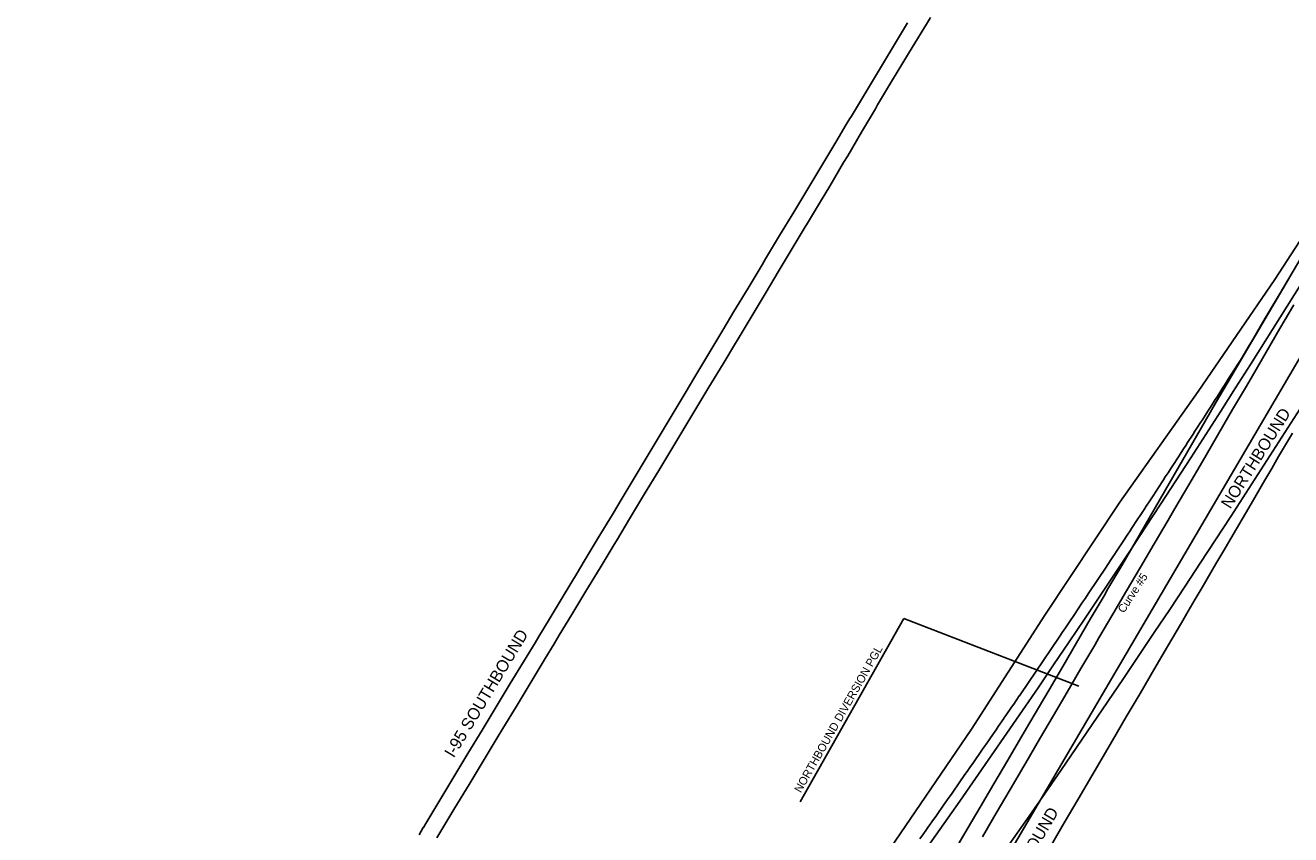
# Model space of a CAD drawing. Extents: x 1160458 to 1162290, y 615427 to 618737.
# Drawn here: x 1161573.3 to 1162037.4, y 618140.3 to 618437 of the extents above; entities that cross this region are included whole.
import ezdxf

# ---------------------------------------------------------------- set-up
doc = ezdxf.new("R2010")
doc.units = 0
for name, color, linetype in [('1', 7, 'Continuous'), ('ANNOTATION', 7, 'Continuous'), ('D_Roadway_Edge_Shoulder', 7, 'Continuous'), ('D_Roadway_Edge_TW', 7, 'Continuous'), ('D_Slope_Fill', 7, 'Continuous'), ('D_Text_Standard', 7, 'Continuous'), ('Old pavement area_not used', 7, 'Continuous'), ('Shoulder work for div plan (NB)', 7, 'Continuous'), ('Shoulder work for div plans (SB)', 7, 'Continuous')]:
    doc.layers.add(name, color=color, linetype=linetype)

msp = doc.modelspace()

# ---------------------------------------------------------------- linework, layer by layer
at = {"layer": '1'}
msp.add_line((1161209.81, 616899.51), (1162286.6, 618733.81), dxfattribs=at)
at = {"layer": 'D_Roadway_Edge_Shoulder'}
msp.add_lwpolyline([(1161901.43, 618138.75), (1161902.72, 618140.58), (1161903.54, 618141.74), (1161904.32, 618142.85), (1161906.43, 618145.84), (1161907.21, 618146.95), (1161908.5, 618148.79), (1161909.31, 618149.95), (1161910.09, 618151.05), (1161912.19, 618154.06), (1161912.97, 618155.16), (1161914.25, 618157), (1161915.07, 618158.17), (1161915.84, 618159.27), (1161917.94, 618162.28), (1161918.71, 618163.38), (1161919.99, 618165.23), (1161920.8, 618166.4), (1161921.57, 618167.5), (1161923.66, 618170.52), (1161924.42, 618171.62), (1161925.36, 618172.97), (1161925.7, 618173.47), (1161926.51, 618174.64), (1161926.54, 618174.67), (1161927.28, 618175.74), (1161929.36, 618178.76), (1161930.12, 618179.87), (1161932.2, 618182.89), (1161932.23, 618182.93), (1161932.96, 618184), (1161935.04, 618187.02), (1161935.8, 618188.13), (1161937.87, 618191.16), (1161937.9, 618191.2), (1161938.63, 618192.27), (1161940.7, 618195.3), (1161941.46, 618196.41), (1161943.53, 618199.44), (1161943.55, 618199.48), (1161944.28, 618200.55), (1161946.35, 618203.59), (1161947.1, 618204.7), (1161949.16, 618207.74), (1161949.18, 618207.77), (1161949.91, 618208.85), (1161951.97, 618211.9), (1161952.72, 618213), (1161953.64, 618214.36), (1161954.77, 618216.05), (1161954.79, 618216.08), (1161955.52, 618217.15), (1161956.51, 618218.64), (1161957.58, 618220.22), (1161958.31, 618221.31), (1161960.37, 618224.38), (1161961.1, 618225.47), (1161962.1, 618226.96), (1161963.16, 618228.55), (1161963.89, 618229.63), (1161965.95, 618232.72), (1161966.67, 618233.8), (1161967.66, 618235.29), (1161968.73, 618236.9), (1161969.44, 618237.97), (1161971.5, 618241.07), (1161972.21, 618242.14), (1161973.04, 618243.39), (1161973.2, 618243.63), (1161976.05, 618247.95), (1161977.44, 618250.04), (1161978.72, 618251.99), (1161978.82, 618252.14), (1161981.39, 618256.05), (1161982.22, 618257.32), (1161983.13, 618258.7), (1161983.91, 618259.89), (1161984.21, 618260.35), (1161985.97, 618263.03), (1161986.95, 618264.54), (1161988.02, 618266.17), (1161988.7, 618267.21), (1161990.75, 618270.36), (1161991.43, 618271.41), (1161992.42, 618272.92), (1161993.48, 618274.55), (1161994.16, 618275.6), (1161996.2, 618278.75), (1161996.88, 618279.8), (1161997.86, 618281.31), (1161998.92, 618282.94), (1161999.6, 618284), (1162001.63, 618287.14), (1162002.31, 618288.2), (1162003.29, 618289.72), (1162004.33, 618291.35), (1162004.35, 618291.37), (1162005.02, 618292.42), (1162007.04, 618295.56), (1162007.72, 618296.63), (1162008.62, 618298.03), (1162009.73, 618299.77), (1162009.75, 618299.8), (1162010.42, 618300.84), (1162012.43, 618303.99), (1162013.11, 618305.06), (1162015.11, 618308.21), (1162015.13, 618308.24), (1162019.8, 618315.58)], dxfattribs=at)
at = {"layer": 'D_Roadway_Edge_TW'}
for radius in [4188, 4212]:
    msp.add_arc((1158484.81, 620553.82), radius, 320.71863, 329.58575, dxfattribs=at)
at = {"layer": 'D_Slope_Fill'}
msp.add_lwpolyline([(1161864.33, 618096.78), (1161892.38, 618137.82), (1161920.38, 618178.92), (1161947.2, 618220.79), (1161974.76, 618262.22), (1162003.5, 618302.78), (1162031.65, 618343.82), (1162058.74, 618385.58), (1162080.66, 618419.35), (1162091.79, 618436.2), (1162091.79, 618436.2)], dxfattribs=at)
at = {"layer": 'D_Text_Standard'}
for p, q in [((1161857.43, 618152.36), (1161895.51, 618219.49)), ((1161895.51, 618219.49), (1161959.65, 618194.7))]:
    msp.add_line(p, q, dxfattribs=at)
at = {"layer": 'Old pavement area_not used'}
for points in [[(1162038.3, 618346.83), (1162033.2, 618338.23), (1162028.1, 618329.63), (1162023.01, 618321.02), (1162022.22, 618319.67), (1162017.16, 618311.05), (1162015.15, 618307.6), (1162010.12, 618298.96), (1162007.84, 618295), (1162002.84, 618286.34), (1161997.84, 618277.68), (1161992.87, 618269.04), (1161987.86, 618260.38), (1161985.49, 618256.3), (1161980.47, 618247.65), (1161975.44, 618239.01), (1161970.4, 618230.37), (1161968.95, 618227.89), (1161963.91, 618219.25), (1161958.86, 618210.62), (1161953.81, 618201.98), (1161948.76, 618193.35), (1161946.83, 618190.06), (1161941.78, 618181.44), (1161936.72, 618172.81), (1161933.64, 618167.57), (1161928.57, 618158.95), (1161923.5, 618150.33), (1161919.14, 618142.92), (1161914.07, 618134.3)], [(1161949.3, 618135.97), (1161954.35, 618144.59), (1161959.41, 618153.22), (1161964.46, 618161.85), (1161972.04, 618174.79), (1161977.1, 618183.42), (1161982.15, 618192.05), (1161987.21, 618200.68), (1161992.26, 618209.31), (1161997.32, 618217.94), (1161999.84, 618222.25), (1162002.37, 618226.57), (1162004.9, 618230.88), (1162009.95, 618239.51), (1162012.48, 618243.82), (1162017.53, 618252.45), (1162022.89, 618261.61), (1162027.94, 618270.24), (1162030.47, 618274.55), (1162033, 618278.87), (1162038.05, 618287.5)]]:
    msp.add_lwpolyline(points, dxfattribs=at)
at = {"layer": 'Shoulder work for div plan (NB)'}
msp.add_line((1162035.75, 618342.53), (1162008.98, 618296.98), dxfattribs=at)
for points in [[(1162073.95, 618408), (1162071.68, 618404.02), (1162069.4, 618400.04), (1162066.43, 618394.87), (1162061.43, 618386.21), (1162060.67, 618384.91), (1162058.15, 618380.58), (1162055.63, 618376.26), (1162052.51, 618370.92), (1162047.43, 618362.29), (1162042.35, 618353.68), (1162038.3, 618346.83), (1162035.75, 618342.53)], [(1161924.35, 618139.51), (1161929.4, 618148.14), (1161934.46, 618156.77), (1161939.51, 618165.4), (1161940.25, 618166.66), (1161945.31, 618175.29), (1161950.36, 618183.92), (1161955.42, 618192.54), (1161960.47, 618201.17), (1161965.54, 618209.8), (1161967.09, 618212.44), (1161972.16, 618221.07), (1161977.22, 618229.69), (1161982.29, 618238.31), (1161987.36, 618246.93), (1161992.42, 618255.55), (1161994.95, 618259.87), (1162000, 618268.5), (1162005.04, 618277.14), (1162010.08, 618285.77), (1162011.07, 618287.46), (1162016.12, 618296.1), (1162021.17, 618304.73), (1162023.41, 618308.55), (1162028.45, 618317.19), (1162033.49, 618325.83), (1162038.52, 618334.47)], [(1162008.98, 618296.98), (1162007.84, 618295), (1162002.84, 618286.34), (1161997.84, 618277.68), (1161992.87, 618269.04), (1161987.86, 618260.38), (1161985.49, 618256.3), (1161980.47, 618247.65), (1161975.44, 618239.01), (1161970.4, 618230.37), (1161968.95, 618227.89), (1161963.91, 618219.25), (1161958.86, 618210.62), (1161953.81, 618201.98), (1161948.76, 618193.35), (1161946.83, 618190.06), (1161941.78, 618181.44), (1161936.72, 618172.81), (1161933.64, 618167.57), (1161928.57, 618158.95), (1161923.5, 618150.33), (1161919.14, 618142.92), (1161915.96, 618137.52)]]:
    msp.add_lwpolyline(points, dxfattribs=at)
at = {"layer": 'Shoulder work for div plans (SB)'}
for p, q in [((1161895.18, 618423.29), (1161898.6, 618428.91)), ((1161891.03, 618416.44), (1161895.18, 618423.29)), ((1161885.91, 618407.85), (1161891.03, 618416.44)), ((1161885.07, 618406.43), (1161885.91, 618407.85)), ((1161875.74, 618402.79), (1161874.41, 618400.59)), ((1161876.26, 618403.65), (1161875.74, 618402.79)), ((1161865.43, 618385.66), (1161860.27, 618377.09)), ((1161868.33, 618378.08), (1161873.42, 618386.69)), ((1161864.94, 618372.4), (1161868.33, 618378.08)), ((1161860.27, 618377.09), (1161855.12, 618368.52)), ((1161855.12, 618368.52), (1161849.96, 618359.95)), ((1161849.96, 618359.95), (1161844.81, 618351.38)), ((1161844.67, 618338.62), (1161849.82, 618347.19)), ((1161838.35, 618340.64), (1161833.2, 618332.07)), ((1161839.51, 618330.05), (1161844.67, 618338.62)), ((1161834.35, 618321.49), (1161839.51, 618330.05)), ((1161829.18, 618312.92), (1161833.74, 618320.48)), ((1161833.74, 618320.48), (1161834.35, 618321.49)), ((1161824.02, 618304.36), (1161829.18, 618312.92)), ((1161818.86, 618308.14), (1161815.27, 618302.15)), ((1161804.99, 618284.99), (1161799.85, 618276.42)), ((1161799.85, 618276.42), (1161797.34, 618272.24)), ((1161797.34, 618272.24), (1161792.2, 618263.66)), ((1161792.2, 618263.66), (1161788.6, 618257.68)), ((1161784.1, 618238.1), (1161789.28, 618246.66)), ((1161778.29, 618240.54), (1161775.75, 618236.33)), ((1161775.75, 618236.33), (1161770.58, 618227.77)), ((1161778.92, 618229.55), (1161784.1, 618238.1)), ((1161773.74, 618221), (1161778.92, 618229.55)), ((1161770.58, 618227.77), (1161765.41, 618219.21)), ((1161765.41, 618219.21), (1161761.63, 618212.96)), ((1161760.24, 618210.65), (1161755.06, 618202.1)), ((1161761.63, 618212.96), (1161760.24, 618210.65)), ((1161755.06, 618202.1), (1161751.17, 618195.65)), ((1161751.17, 618195.65), (1161745.99, 618187.1)), ((1161753.62, 618187.72), (1161758.78, 618196.28)), ((1161748.45, 618179.16), (1161753.62, 618187.72)), ((1161745.99, 618187.1), (1161740.82, 618178.54)), ((1161740.82, 618178.54), (1161735.64, 618169.98)), ((1161746.39, 618175.75), (1161748.45, 618179.16)), ((1161735.64, 618169.98), (1161730.47, 618161.42)), ((1161730.47, 618161.42), (1161725.3, 618152.87)), ((1161725.3, 618152.87), (1161720.12, 618144.31)), ((1161719.24, 618142.84), (1161717.68, 618140.26)), ((1161719.3, 618142.94), (1161719.24, 618142.84)), ((1161720.12, 618144.31), (1161719.3, 618142.94)), ((1161724.24, 618139.12), (1161725.69, 618141.52))]:
    msp.add_line(p, q, dxfattribs=at)
for points in [[(1161898.6, 618428.91), (1161903.8, 618437.46), (1161905.29, 618439.91)], [(1161896.89, 618437.92), (1161891.73, 618429.35), (1161886.57, 618420.78)], [(1161886.57, 618420.78), (1161881.41, 618412.22), (1161876.26, 618403.65)], [(1161879.97, 618397.81), (1161879.98, 618397.82), (1161885.07, 618406.43)], [(1161874.41, 618400.59), (1161870.58, 618394.23), (1161865.43, 618385.66)], [(1161873.42, 618386.69), (1161874.91, 618389.2), (1161879.97, 618397.81)], [(1161849.82, 618347.19), (1161854.6, 618355.13), (1161859.74, 618363.7), (1161859.81, 618363.81), (1161864.94, 618372.4)], [(1161844.81, 618351.38), (1161843.5, 618349.21), (1161838.35, 618340.64)], [(1161833.2, 618332.07), (1161829.14, 618325.29), (1161824, 618316.71), (1161818.86, 618308.14)], [(1161810.74, 618282.33), (1161813.69, 618287.23), (1161818.86, 618295.79), (1161824.02, 618304.36)], [(1161815.27, 618302.15), (1161810.13, 618293.57), (1161804.99, 618284.99)], [(1161789.28, 618246.66), (1161790.12, 618248.05), (1161795.28, 618256.62), (1161800.43, 618265.19), (1161805.59, 618273.76), (1161810.74, 618282.33)], [(1161788.6, 618257.68), (1161783.45, 618249.11), (1161778.29, 618240.54)], [(1161767.22, 618210.23), (1161769.13, 618213.4), (1161773.74, 618221)], [(1161758.78, 618196.28), (1161763.96, 618204.84), (1161767.22, 618210.23)], [(1161736.04, 618158.63), (1161741.21, 618167.19), (1161746.39, 618175.75)], [(1161725.69, 618141.52), (1161730.86, 618150.08), (1161736.04, 618158.63)]]:
    msp.add_lwpolyline(points, dxfattribs=at)

# ---------------------------------------------------------------- texts
at = {"layer": 'ANNOTATION'}
msp.add_text('Curve #5', height=3, rotation=56.7425, dxfattribs=at).set_placement((1161976.24, 618221.28))
at = {"layer": 'D_Text_Standard'}
for s, height, rotation, p in [('NORTHBOUND', 4.375, 57.7894, (1162015.28, 618259.44)), ('I-95 SOUTHBOUND', 4.375, 58.9419, (1161730.42, 618168.16)), ('NORTHBOUND DIVERSION PGL', 3, 60.4348, (1161857.72, 618155.4)), ('I-95 NORTHBOUND', 4.375, 59.6079, (1161925.34, 618102.38))]:
    msp.add_text(s, height=height, rotation=rotation, dxfattribs=at).set_placement(p)

doc.saveas('drawing.dxf')
